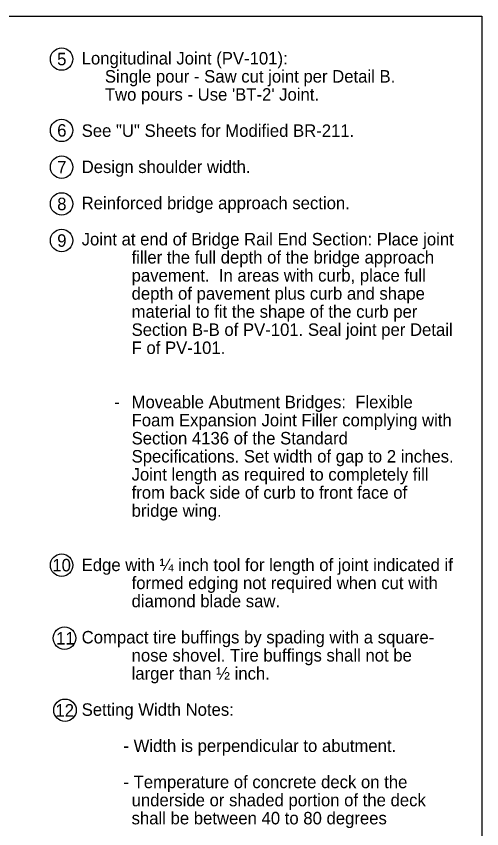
# Model space of a CAD drawing. Extents: x 10130 to 81668, y 5440 to 21644.
# Drawn here: x 19722 to 20468, y 8642 to 9944 of the extents above; entities that cross this region are included whole.
import ezdxf

# ---------------------------------------------------------------- set-up
doc = ezdxf.new("R2010")
doc.units = 0
for name, color, linetype in [('dsnStdBlockModified', 7, 'Continuous'), ('dsnStdBorder', 7, 'Continuous'), ('Level 5', 7, 'Continuous'), ('SheetBorder', 7, 'Continuous')]:
    doc.layers.add(name, color=color, linetype=linetype)

msp = doc.modelspace()

# ---------------------------------------------------------------- linework, layer by layer
at = {"layer": 'dsnStdBorder'}
for centre in [(19794.5, 9875.4), (19794.5, 9761.1), (19794.5, 9702.1), (19794.5, 9643.2), (19794.5, 9584.5), (19794.5, 9064.2), (19799.1, 8947.1), (19799.9, 8831.6)]:
    msp.add_circle(centre, 18, dxfattribs=at)
at = {"layer": 'SheetBorder'}
msp.add_lwpolyline([(17332.5, 9944), (20467.5, 9944), (20467.5, 7924), (17332.5, 7924)], close=True, dxfattribs=at)

# ---------------------------------------------------------------- texts
at = {"layer": 'dsnStdBlockModified'}
for s, p in [('10', (19779.6, 9054.2)), ('11', (19785.6, 8937)), ('12', (19784.6, 8821.5))]:
    msp.add_text(s, height=20, dxfattribs=at).set_placement(p)
at = {"layer": 'Level 5'}
for s, p in [('5', (19787.3, 9865.4)), ('Longitudinal Joint (PV-101):', (19826.6, 9866.7)), ('     Single pour - Saw cut joint per Detail B.', (19826.6, 9837.7)), ("     Two pours - Use 'BT-2' Joint.", (19826.6, 9808.7)), ('6', (19787.4, 9751.1)), ('See "U" Sheets for Modified BR-211.', (19826.6, 9750.7)), ('7', (19787.4, 9692.1)), ('Design shoulder width.', (19826.6, 9692.7)), ('8', (19787.4, 9633.2)), ('Reinforced bridge approach section.', (19826.6, 9634.7)), ('9', (19787.4, 9574.5)), ('Joint at end of Bridge Rail End Section: Place joint ', (19826.6, 9576.7)), ('filler the full depth of the bridge approach ', (19906.6, 9547.7)), ('pavement.  In areas with curb, place full ', (19906.6, 9518.7)), ('depth of pavement plus curb and shape ', (19906.6, 9489.7)), ('material to fit the shape of the curb per ', (19906.6, 9460.7)), ('Section B-B of PV-101. Seal joint per Detail ', (19906.6, 9431.7)), ('F of PV-101.', (19906.6, 9402.7)), ('Moveable Abutment Bridges:  Flexible ', (19906.6, 9315.7)), ('       -', (19826.6, 9315.7)), ('Foam Expansion Joint Filler complying with ', (19906.6, 9286.7)), ('Section 4136 of the Standard ', (19906.6, 9257.7)), ('Specifications. Set width of gap to 2 inches.  ', (19906.6, 9228.7)), ('Joint length as required to completely fill ', (19906.6, 9199.7)), ('from back side of curb to front face of ', (19906.6, 9170.7)), ('bridge wing.', (19906.6, 9141.7)), ('Edge with ¼ inch tool for length of joint indicated if ', (19826.6, 9054.7)), ('formed edging not required when cut with ', (19906.6, 9025.7)), ('diamond blade saw.', (19906.6, 8996.7)), ('Compact tire buffings by spading with a square-', (19826.6, 8938.7)), ('nose shovel. Tire buffings shall not be ', (19906.6, 8909.7)), ('larger than ½ inch.', (19906.6, 8880.7)), ('Setting Width Notes:', (19826.6, 8822.7)), ('         - Width is perpendicular to abutment.', (19826.6, 8764.7)), ('         - Temperature of concrete deck on the ', (19826.6, 8706.7)), ('underside or shaded portion of the deck ', (19906.6, 8677.7)), ('shall be between 40 to 80 degrees ', (19906.6, 8648.7))]:
    msp.add_text(s, height=20, dxfattribs=at).set_placement(p)

doc.saveas('drawing.dxf')
